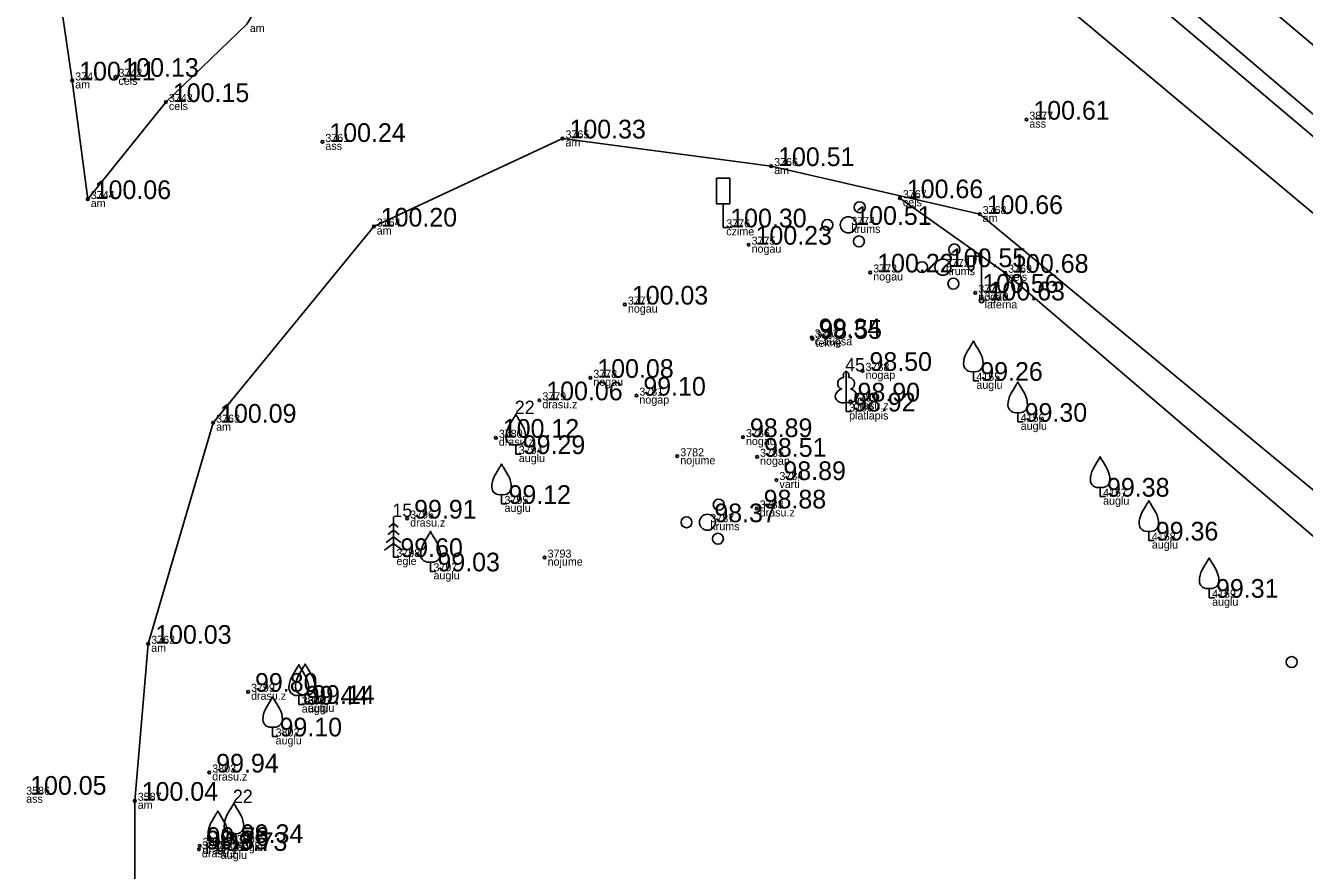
# Model space of a CAD drawing. Extents: x 614911 to 615803, y 262110 to 264311.
# Drawn here: x 615612.66 to 615660.6, y 264118.54 to 264150.2 of the extents above; entities that cross this region are included whole.
import ezdxf

# ---------------------------------------------------------------- set-up
doc = ezdxf.new("R2010")
doc.units = 0
for name, color, linetype in [('Level 1', 7, 'Continuous'), ('Level 16', 7, 'Continuous'), ('Level 31', 7, 'Continuous'), ('Level 37', 7, 'Continuous'), ('Level 44', 7, 'Continuous'), ('Level 53', 7, 'Continuous'), ('Level 54', 7, 'Continuous'), ('Level 57', 7, 'Continuous'), ('Level 58', 7, 'Continuous')]:
    doc.layers.add(name, color=color, linetype=linetype)

msp = doc.modelspace()

# ---------------------------------------------------------------- linework, layer by layer
at = {"layer": 'Level 1'}
for p, q in [((615648.185, 264137.239), (615648.185, 264136.887)), ((615648.185, 264136.887), (615648.385, 264136.887)), ((615643.416, 264136.085), (615643.416, 264135.738)), ((615643.416, 264135.738), (615643.616, 264135.738)), ((615649.848, 264135.704), (615649.848, 264135.352)), ((615649.848, 264135.352), (615650.048, 264135.352)), ((615631.034, 264134.495), (615631.034, 264134.143)), ((615631.034, 264134.143), (615631.234, 264134.143)), ((615630.498, 264132.629), (615630.498, 264132.277)), ((615652.936, 264132.899), (615652.936, 264132.547)), ((615652.936, 264132.547), (615653.136, 264132.547)), ((615630.498, 264132.277), (615630.698, 264132.277)), ((615626.445, 264131.786), (615626.445, 264130.286)), ((615626.445, 264131.286), (615626.229, 264131.128)), ((615626.445, 264131.536), (615626.269, 264131.408)), ((615626.445, 264131.536), (615626.619, 264131.408)), ((615626.445, 264131.286), (615626.661, 264131.128)), ((615654.765, 264131.256), (615654.765, 264130.904)), ((615626.445, 264130.786), (615626.113, 264130.542)), ((615626.445, 264131.036), (615626.167, 264130.832)), ((615626.445, 264131.036), (615626.723, 264130.832)), ((615626.445, 264130.786), (615626.779, 264130.542)), ((615654.765, 264130.904), (615654.965, 264130.904)), ((615626.445, 264130.286), (615626.645, 264130.286)), ((615627.835, 264130.1), (615627.835, 264129.748)), ((615627.835, 264129.748), (615628.035, 264129.748)), ((615657.022, 264129.112), (615657.022, 264128.76)), ((615657.022, 264128.76), (615657.222, 264128.76)), ((615622.896, 264125.108), (615622.896, 264124.756)), ((615623.138, 264125.136), (615623.138, 264124.784)), ((615622.896, 264124.756), (615623.096, 264124.756)), ((615623.138, 264124.784), (615623.338, 264124.784)), ((615621.917, 264123.917), (615621.917, 264123.565)), ((615621.917, 264123.565), (615622.117, 264123.565)), ((615619.865, 264119.628), (615619.865, 264119.276)), ((615620.466, 264119.922), (615620.466, 264119.57)), ((615619.865, 264119.276), (615620.065, 264119.276)), ((615620.466, 264119.57), (615620.666, 264119.57))]:
    msp.add_line(p, q, dxfattribs=at)
for points in [[(615643.416, 264137.238), (615643.416, 264136.085)], [(615643.506, 264137.006), (615643.505, 264137.007)]]:
    msp.add_lwpolyline(points, dxfattribs=at)
for centre, radius in [((615643.925, 264143.39), 0.207), ((615642.714, 264142.73), 0.204), ((615643.498, 264142.73), 0.301), ((615643.893, 264142.11), 0.205), ((615647.47, 264141.806), 0.207), ((615646.259, 264141.146), 0.204), ((615647.043, 264141.146), 0.301), ((615647.438, 264140.526), 0.205), ((615638.642, 264132.249), 0.207), ((615637.431, 264131.589), 0.204), ((615638.215, 264131.589), 0.301), ((615638.61, 264130.969), 0.205), ((615660.117, 264126.35), 0.204)]:
    msp.add_circle(centre, radius, dxfattribs=at)
for centre, radius, start, end in [((615647.768, 264138.525), 0.439, 324.3837, 341.712), ((615648.602, 264138.525), 0.439, 198.288, 215.6163), ((615648.709, 264137.512), 0.89, 151.757, 179.9138), ((615660.81, 264130.491), 14.88, 148.4844, 149.9901), ((615635.56, 264130.491), 14.88, 30.0099, 31.5156), ((615647.661, 264137.512), 0.89, 0.0862, 28.243), ((615648.109, 264137.518), 0.29, 181.0782, 285.2823), ((615648.261, 264137.518), 0.29, 254.7177, 358.9218), ((615649.431, 264136.99), 0.439, 324.3837, 341.712), ((615650.265, 264136.99), 0.439, 198.288, 215.6163), ((615650.372, 264135.977), 0.89, 151.757, 179.9138), ((615662.473, 264128.956), 14.88, 148.4844, 149.9901), ((615637.223, 264128.956), 14.88, 30.0099, 31.5156), ((615649.324, 264135.977), 0.89, 0.0862, 28.243), ((615649.772, 264135.983), 0.29, 181.0782, 285.2823), ((615649.924, 264135.983), 0.29, 254.7177, 358.9218), ((615643.659, 264127.747), 14.88, 148.4844, 149.9901), ((615630.617, 264135.781), 0.439, 324.3837, 341.712), ((615631.451, 264135.781), 0.439, 198.288, 215.6163), ((615618.409, 264127.747), 14.88, 30.0099, 31.5156), ((615631.558, 264134.768), 0.89, 151.757, 179.9138), ((615630.51, 264134.768), 0.89, 0.0862, 28.243), ((615630.958, 264134.774), 0.29, 181.0782, 285.2823), ((615631.11, 264134.774), 0.29, 254.7177, 358.9218), ((615652.519, 264134.185), 0.439, 324.3837, 341.712), ((615653.353, 264134.185), 0.439, 198.288, 215.6163), ((615643.123, 264125.881), 14.88, 148.4844, 149.9901), ((615630.081, 264133.915), 0.439, 324.3837, 341.712), ((615630.915, 264133.915), 0.439, 198.288, 215.6163), ((615617.873, 264125.881), 14.88, 30.0099, 31.5156), ((615653.46, 264133.172), 0.89, 151.757, 179.9138), ((615665.561, 264126.151), 14.88, 148.4844, 149.9901), ((615640.311, 264126.151), 14.88, 30.0099, 31.5156), ((615652.412, 264133.172), 0.89, 0.0862, 28.243), ((615631.022, 264132.902), 0.89, 151.757, 179.9138), ((615629.974, 264132.902), 0.89, 0.0862, 28.243), ((615652.86, 264133.178), 0.29, 181.0782, 285.2823), ((615653.012, 264133.178), 0.29, 254.7177, 358.9218), ((615630.422, 264132.908), 0.29, 181.0782, 285.2823), ((615630.574, 264132.908), 0.29, 254.7177, 358.9218), ((615667.39, 264124.508), 14.88, 148.4844, 149.9901), ((615654.348, 264132.542), 0.439, 324.3837, 341.712), ((615655.182, 264132.542), 0.439, 198.288, 215.6163), ((615642.14, 264124.508), 14.88, 30.0099, 31.5156), ((615655.289, 264131.529), 0.89, 151.757, 179.9138), ((615654.241, 264131.529), 0.89, 0.0862, 28.243), ((615640.46, 264123.352), 14.88, 148.4844, 149.9901), ((615627.418, 264131.386), 0.439, 324.3837, 341.712), ((615628.252, 264131.386), 0.439, 198.288, 215.6163), ((615615.21, 264123.352), 14.88, 30.0099, 31.5156), ((615654.689, 264131.535), 0.29, 181.0782, 285.2823), ((615654.841, 264131.535), 0.29, 254.7177, 358.9218), ((615628.359, 264130.373), 0.89, 151.757, 179.9138), ((615627.311, 264130.373), 0.89, 0.0862, 28.243), ((615627.759, 264130.379), 0.29, 181.0782, 285.2823), ((615627.911, 264130.379), 0.29, 254.7177, 358.9218), ((615669.647, 264122.364), 14.88, 148.4844, 149.9901), ((615656.605, 264130.398), 0.439, 324.3837, 341.712), ((615657.439, 264130.398), 0.439, 198.288, 215.6163), ((615644.397, 264122.364), 14.88, 30.0099, 31.5156), ((615657.546, 264129.385), 0.89, 151.757, 179.9138), ((615656.498, 264129.385), 0.89, 0.0862, 28.243), ((615656.946, 264129.391), 0.29, 181.0782, 285.2823), ((615657.098, 264129.391), 0.29, 254.7177, 358.9218), ((615635.521, 264118.36), 14.88, 148.4844, 149.9901), ((615623.662, 264125.409), 0.89, 151.757, 179.9138), ((615622.479, 264126.394), 0.439, 324.3837, 341.712), ((615635.763, 264118.388), 14.88, 148.4844, 149.9901), ((615623.313, 264126.394), 0.439, 198.288, 215.6163), ((615610.271, 264118.36), 14.88, 30.0099, 31.5156), ((615622.721, 264126.422), 0.439, 324.3837, 341.712), ((615623.555, 264126.422), 0.439, 198.288, 215.6163), ((615610.513, 264118.388), 14.88, 30.0099, 31.5156), ((615622.614, 264125.409), 0.89, 0.0862, 28.243), ((615623.42, 264125.381), 0.89, 151.757, 179.9138), ((615622.82, 264125.387), 0.29, 181.0782, 285.2823), ((615623.062, 264125.415), 0.29, 181.0782, 285.2823), ((615622.972, 264125.387), 0.29, 254.7177, 358.9218), ((615623.214, 264125.415), 0.29, 254.7177, 358.9218), ((615622.372, 264125.381), 0.89, 0.0862, 28.243), ((615634.542, 264117.169), 14.88, 148.4844, 149.9901), ((615621.5, 264125.203), 0.439, 324.3837, 341.712), ((615622.334, 264125.203), 0.439, 198.288, 215.6163), ((615609.292, 264117.169), 14.88, 30.0099, 31.5156), ((615622.441, 264124.19), 0.89, 151.757, 179.9138), ((615621.393, 264124.19), 0.89, 0.0862, 28.243), ((615621.841, 264124.196), 0.29, 181.0782, 285.2823), ((615621.993, 264124.196), 0.29, 254.7177, 358.9218), ((615620.049, 264121.208), 0.439, 324.3837, 341.712), ((615620.883, 264121.208), 0.439, 198.288, 215.6163), ((615632.49, 264112.88), 14.88, 148.4844, 149.9901), ((615619.448, 264120.914), 0.439, 324.3837, 341.712), ((615620.282, 264120.914), 0.439, 198.288, 215.6163), ((615607.24, 264112.88), 14.88, 30.0099, 31.5156), ((615620.99, 264120.195), 0.89, 151.757, 179.9138), ((615633.091, 264113.174), 14.88, 148.4844, 149.9901), ((615607.841, 264113.174), 14.88, 30.0099, 31.5156), ((615619.942, 264120.195), 0.89, 0.0862, 28.243), ((615620.389, 264119.901), 0.89, 151.757, 179.9138), ((615620.39, 264120.201), 0.29, 181.0782, 285.2823), ((615619.341, 264119.901), 0.89, 0.0862, 28.243), ((615620.542, 264120.201), 0.29, 254.7177, 358.9218), ((615619.789, 264119.907), 0.29, 181.0782, 285.2823), ((615619.941, 264119.907), 0.29, 254.7177, 358.9218)]:
    msp.add_arc(centre, radius, start, end, dxfattribs=at)
for centre, major_axis, ratio, start_param, end_param in [((615643.288, 264136.793), (-0.039, -0.212), 0.861323, 3.141593, 6.283185), ((615643.416, 264137.088), (0, -0.15), 0.707107, 3.14537, 5.287485), ((615643.416, 264137.088), (0, -0.15), 0.707107, 0.995701, 3.137816), ((615643.544, 264136.793), (0.039, -0.212), 0.861323, 0, 3.141593), ((615643.326, 264136.331), (0.307, 0.095), 0.814445, 1.570796, 4.752015), ((615643.506, 264136.331), (-0.307, 0.095), 0.814445, 1.531171, 4.712389)]:
    msp.add_ellipse(centre, major_axis=major_axis, ratio=ratio, start_param=start_param, end_param=end_param, dxfattribs=at)
at = {"layer": 'Level 16'}
for p, q in [((615639.057, 264144.483), (615638.557, 264144.483)), ((615638.557, 264143.514), (615638.557, 264144.483)), ((615639.057, 264143.514), (615639.057, 264144.483)), ((615639.057, 264143.514), (615638.557, 264143.514)), ((615638.811, 264143.514), (615638.811, 264142.636)), ((615638.811, 264142.636), (615639.126, 264142.636))]:
    msp.add_line(p, q, dxfattribs=at)
at = {"layer": 'Level 31'}
for points in [[(615744.764, 264081.359), (615732.887, 264089.943), (615715.889, 264102.764), (615694.682, 264119.208), (615676.974, 264133.244), (615650.72, 264155.552), (615629.606, 264174.135), (615612.305, 264190.628), (615596.307, 264206.969), (615581.341, 264223.238), (615571.304, 264233.709), (615558.243, 264246.987), (615542.242, 264265.322), (615529.994, 264284)], [(615573.297, 264235.218), (615582.765, 264223.901), (615598.169, 264208.795), (615613.95, 264192.439), (615631.402, 264176.068), (615651.799, 264157.165), (615678.305, 264134.819), (615695.98, 264121.225), (615717.243, 264104.936), (615734.373, 264091.846), (615746.465, 264082.76)]]:
    msp.add_lwpolyline(points, dxfattribs=at)
at = {"layer": 'Level 37'}
for points in [[(615526.871, 264279.709), (615557.508, 264246.916), (615570.946, 264232.844), (615580.588, 264222.695), (615595.945, 264206.676), (615612.011, 264190.126), (615629.214, 264173.64), (615650.344, 264154.99), (615676.59, 264132.802), (615694.345, 264118.703), (615715.543, 264102.359), (615732.654, 264089.574), (615744.576, 264080.858)], [(615743.178, 264079.076), (615731.345, 264087.792), (615714.316, 264100.575), (615693.008, 264116.957), (615675.219, 264131.222), (615649.561, 264152.667), (615627.765, 264171.974), (615611.182, 264188.292), (615594.351, 264205.525), (615579.137, 264221.33), (615569.398, 264231.353), (615556.134, 264245.272), (615540.03, 264262.148), (615525.148, 264277.969)], [(615618.44, 264167.909), (615617.516, 264167.323), (615614.758, 264163.326), (615613.202, 264159.576), (615613.435, 264154.711), (615614.405, 264148.14), (615614.987, 264143.696), (615617.917, 264147.331), (615620.949, 264150.253), (615625.11, 264157.041), (615625.853, 264159.976), (615625.734, 264162.896), (615620.295, 264168.102)], [(615625.063, 264106.562), (615623.229, 264104.588), (615622.747, 264105.634), (615621.37, 264105.71), (615619.131, 264107.71), (615616.734, 264111.901), (615616.748, 264121.153), (615617.254, 264127.034), (615619.687, 264135.318), (615625.708, 264142.666), (615632.784, 264145.968), (615640.605, 264144.932), (615648.422, 264143.136), (615670.375, 264124.985), (615688.06, 264110.762), (615709.564, 264094.167), (615727.03, 264081.038), (615738.779, 264072.364)], [(615737.997, 264071.23), (615726.411, 264079.821), (615708.486, 264093), (615687.279, 264109.494), (615669.461, 264123.776), (615649.379, 264140.934), (615645.431, 264143.727)]]:
    msp.add_lwpolyline(points, dxfattribs=at)
at = {"layer": 'Level 44'}
for p, q in [((615648.494, 264139.9), (615648.494, 264141.783)), ((615648.494, 264141.563), (615647.859, 264141.563)), ((615647.994, 264141.563), (615647.994, 264141.171)), ((615648.204, 264141.563), (615648.204, 264141.171))]:
    msp.add_line(p, q, dxfattribs=at)
msp.add_circle((615648.494, 264139.9), 0.09, dxfattribs=at)
msp.add_ellipse((615648.099, 264141.171), major_axis=(0, 0.151), ratio=0.695971, start_param=1.570796, end_param=4.712389, dxfattribs=at)
at = {"layer": 'Level 57'}
for centre in [(615614.405, 264148.14), (615616.025, 264148.276), (615617.917, 264147.331), (615650.173, 264146.671), (615632.784, 264145.968), (615623.782, 264145.837), (615640.605, 264144.932), (615614.987, 264143.696), (615645.431, 264143.727), (615648.422, 264143.136), (615625.708, 264142.666), (615639.76, 264141.987), (615644.32, 264140.946), (615649.379, 264140.934), (615648.257, 264140.184), (615635.123, 264139.743), (615642.124, 264138.514), (615642.156, 264138.461), (615633.828, 264136.999), (615644.031, 264137.259), (615635.554, 264136.332), (615631.915, 264136.157), (615643.583, 264136.113), (615619.687, 264135.318), (615630.285, 264134.754), (615639.548, 264134.778), (615637.086, 264134.06), (615640.077, 264134.041), (615640.804, 264133.169), (615640.064, 264132.105), (615626.961, 264131.727), (615632.113, 264130.264), (615617.254, 264127.034), (615620.996, 264125.237), (615619.542, 264122.212), (615616.748, 264121.153), (615619.155, 264119.332), (615619.182, 264119.463)]:
    msp.add_circle(centre, 0.05, dxfattribs=at)
at = {"layer": 'Level 58'}
for centre in [(615614.405, 264148.14), (615616.025, 264148.276), (615617.917, 264147.331), (615650.173, 264146.671), (615632.784, 264145.968), (615623.782, 264145.837), (615640.605, 264144.932), (615614.987, 264143.696), (615645.431, 264143.727), (615648.422, 264143.136), (615625.708, 264142.666), (615639.76, 264141.987), (615644.32, 264140.946), (615649.379, 264140.934), (615648.257, 264140.184), (615635.123, 264139.743), (615642.124, 264138.514), (615642.156, 264138.461), (615633.828, 264136.999), (615644.031, 264137.259), (615635.554, 264136.332), (615631.915, 264136.157), (615643.583, 264136.113), (615619.687, 264135.318), (615630.285, 264134.754), (615639.548, 264134.778), (615637.086, 264134.06), (615640.077, 264134.041), (615640.804, 264133.169), (615640.064, 264132.105), (615626.961, 264131.727), (615632.113, 264130.264), (615617.254, 264127.034), (615620.996, 264125.237), (615619.542, 264122.212), (615616.748, 264121.153), (615619.155, 264119.332), (615619.182, 264119.463)]:
    msp.add_circle(centre, 0.05, dxfattribs=at)

# ---------------------------------------------------------------- texts
at = {"layer": 'Level 1'}
for s, p in [(' 45', (615643.191, 264137.238)), (' 22', (615630.809, 264135.643)), (' 15', (615626.22, 264131.786)), (' 22', (615620.241, 264121.07))]:
    msp.add_text(s, height=0.5, dxfattribs=at).set_placement(p)
at = {"layer": 'Level 53'}
for s, p in [(' am', (615620.949, 264149.953)), (' am', (615614.405, 264147.84)), (' cels', (615616.025, 264147.976)), (' cels', (615617.917, 264147.031)), (' ass', (615650.173, 264146.371)), (' ass', (615623.782, 264145.537)), (' am', (615632.784, 264145.668)), (' am', (615640.605, 264144.632)), (' am', (615614.987, 264143.396)), (' cels', (615645.431, 264143.427)), (' czime', (615638.811, 264142.336)), (' krums', (615643.498, 264142.43)), (' am', (615648.422, 264142.836)), (' am', (615625.708, 264142.366)), (' nogau', (615639.76, 264141.687)), (' nogau', (615644.32, 264140.646)), (' krums', (615647.043, 264140.846)), (' cels', (615649.379, 264140.634)), (' nogau', (615648.257, 264139.884)), (' laterna', (615648.494, 264139.6)), (' nogau', (615635.123, 264139.443)), (' c.augsa', (615642.124, 264138.214)), (' tekne', (615642.156, 264138.161)), (' nogau', (615633.828, 264136.699)), (' nogap', (615644.031, 264136.959)), (' auglu', (615648.185, 264136.587)), (' drasu.z', (615631.915, 264135.857)), (' nogap', (615635.554, 264136.032)), (' drasu.z', (615643.583, 264135.813)), (' platlapis', (615643.416, 264135.438)), (' am', (615619.687, 264135.018)), (' auglu', (615649.848, 264135.052)), (' drasu.z', (615630.285, 264134.454)), (' nogau', (615639.548, 264134.478)), (' auglu', (615631.034, 264133.843)), (' nojume', (615637.086, 264133.76)), (' nogap', (615640.077, 264133.741)), (' varti', (615640.804, 264132.869)), (' auglu', (615652.936, 264132.247)), (' auglu', (615630.498, 264131.977)), (' drasu.z', (615640.064, 264131.805)), (' drasu.z', (615626.961, 264131.427)), (' krums', (615638.215, 264131.289)), (' auglu', (615654.765, 264130.604)), (' egle', (615626.445, 264129.986)), (' nojume', (615632.113, 264129.964)), (' auglu', (615627.835, 264129.448)), (' auglu', (615657.022, 264128.46)), (' am', (615617.254, 264126.734)), (' drasu.z', (615620.996, 264124.937)), (' auglu', (615622.896, 264124.456)), (' auglu', (615623.138, 264124.484)), (' auglu', (615621.917, 264123.265)), (' drasu.z', (615619.542, 264121.912)), (' ass', (615612.567, 264121.079)), (' am', (615616.748, 264120.853)), (' drasu.z', (615619.155, 264119.032)), (' drasu.z', (615619.182, 264119.163)), (' auglu', (615619.865, 264118.976)), (' auglu', (615620.466, 264119.27))]:
    msp.add_text(s, height=0.3, dxfattribs=at).set_placement(p)
at = {"layer": 'Level 54'}
for s, p in [(' 3741', (615614.405, 264148.14)), (' 3742', (615616.025, 264148.276)), (' 3743', (615617.917, 264147.331)), (' 3877', (615650.173, 264146.671)), (' 3761', (615623.782, 264145.837)), (' 3765', (615632.784, 264145.968)), (' 3766', (615640.605, 264144.932)), (' 3744', (615614.987, 264143.696)), (' 3767', (615645.431, 264143.727)), (' 3768', (615648.422, 264143.136)), (' 3764', (615625.708, 264142.666)), (' 3776', (615638.811, 264142.636)), (' 3774', (615643.498, 264142.73)), (' 3775', (615639.76, 264141.987)), (' 3773', (615644.32, 264140.946)), (' 3772', (615647.043, 264141.146)), (' 3769', (615649.379, 264140.934)), (' 3771', (615648.257, 264140.184)), (' 3777', (615635.123, 264139.743)), (' 3770', (615648.494, 264139.9)), (' 3792', (615642.124, 264138.514)), (' 3791', (615642.156, 264138.461)), (' 3788', (615644.031, 264137.259)), (' 3778', (615633.828, 264136.999)), (' 4155', (615648.185, 264136.887)), (' 3779', (615631.915, 264136.157)), (' 3781', (615635.554, 264136.332)), (' 3789', (615643.583, 264136.113)), (' 3790', (615643.416, 264135.738)), (' 3763', (615619.687, 264135.318)), (' 4156', (615649.848, 264135.352)), (' 3780', (615630.285, 264134.754)), (' 3786', (615639.548, 264134.778)), (' 3794', (615631.034, 264134.143)), (' 3782', (615637.086, 264134.06)), (' 3785', (615640.077, 264134.041)), (' 3784', (615640.804, 264133.169)), (' 3795', (615630.498, 264132.277)), (' 4157', (615652.936, 264132.547)), (' 3783', (615640.064, 264132.105)), (' 3796', (615626.961, 264131.727)), (' 3787', (615638.215, 264131.589)), (' 4158', (615654.765, 264130.904)), (' 3798', (615626.445, 264130.286)), (' 3793', (615632.113, 264130.264)), (' 3797', (615627.835, 264129.748)), (' 4159', (615657.022, 264128.76)), (' 3762', (615617.254, 264127.034)), (' 3799', (615620.996, 264125.237)), (' 3800', (615622.896, 264124.756)), (' 3801', (615623.138, 264124.784)), (' 3802', (615621.917, 264123.565)), (' 3803', (615619.542, 264122.212)), (' 3586', (615612.567, 264121.379)), (' 3587', (615616.748, 264121.153)), (' 3588', (615619.155, 264119.332)), (' 3804', (615619.182, 264119.463)), (' 3805', (615620.466, 264119.57)), (' 3589', (615619.865, 264119.276))]:
    msp.add_text(s, height=0.3, dxfattribs=at).set_placement(p)
at = {"layer": 'Level 58'}
for s, p in [(' 100.11', (615614.405, 264148.14)), (' 100.13', (615616.025, 264148.276)), (' 100.15', (615617.917, 264147.331)), (' 100.61', (615650.173, 264146.671)), (' 100.24', (615623.782, 264145.837)), (' 100.33', (615632.784, 264145.968)), (' 100.51', (615640.605, 264144.932)), (' 100.06', (615614.987, 264143.696)), (' 100.66', (615645.431, 264143.727)), (' 100.66', (615648.422, 264143.136)), (' 100.20', (615625.708, 264142.666)), (' 100.30', (615638.811, 264142.636)), (' 100.51', (615643.498, 264142.73)), (' 100.23', (615639.76, 264141.987)), (' 100.22', (615644.32, 264140.946)), (' 100.55', (615647.043, 264141.146)), (' 100.68', (615649.379, 264140.934)), (' 100.56', (615648.257, 264140.184)), (' 100.03', (615635.123, 264139.743)), (' 100.63', (615648.494, 264139.9)), (' 99.34', (615642.124, 264138.514)), (' 98.55', (615642.156, 264138.461)), (' 98.50', (615644.031, 264137.259)), (' 100.08', (615633.828, 264136.999)), (' 99.26', (615648.185, 264136.887)), (' 100.06', (615631.915, 264136.157)), (' 99.10', (615635.554, 264136.332)), (' 98.92', (615643.416, 264135.738)), (' 98.90', (615643.583, 264136.113)), (' 100.09', (615619.687, 264135.318)), (' 99.30', (615649.848, 264135.352)), (' 100.12', (615630.285, 264134.754)), (' 98.89', (615639.548, 264134.778)), (' 99.29', (615631.034, 264134.143)), (' 98.51', (615640.077, 264134.041)), (' 98.89', (615640.804, 264133.169)), (' 99.38', (615652.936, 264132.547)), (' 99.12', (615630.498, 264132.277)), (' 98.88', (615640.064, 264132.105)), (' 99.91', (615626.961, 264131.727)), (' 98.37', (615638.215, 264131.589)), (' 99.36', (615654.765, 264130.904)), (' 99.60', (615626.445, 264130.286)), (' 99.03', (615627.835, 264129.748)), (' 99.31', (615657.022, 264128.76)), (' 100.03', (615617.254, 264127.034)), (' 99.80', (615620.996, 264125.237)), (' 99.44', (615622.896, 264124.756)), (' 99.14', (615623.138, 264124.784)), (' 99.10', (615621.917, 264123.565)), (' 99.94', (615619.542, 264122.212)), (' 100.05', (615612.567, 264121.379)), (' 100.04', (615616.748, 264121.153)), (' 99.76', (615619.182, 264119.463)), (' 99.34', (615620.466, 264119.57)), (' 99.85', (615619.155, 264119.332)), (' 99.73', (615619.865, 264119.276))]:
    msp.add_text(s, height=0.7, dxfattribs=at).set_placement(p)

doc.saveas('drawing.dxf')
